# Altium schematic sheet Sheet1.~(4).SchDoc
size A4
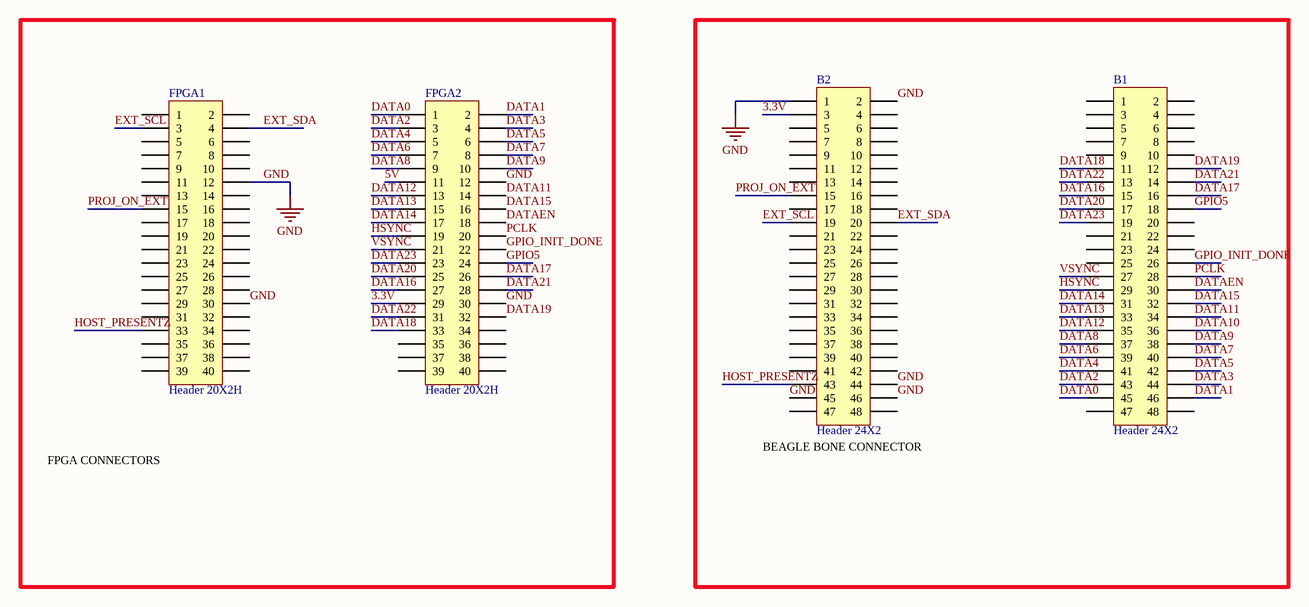
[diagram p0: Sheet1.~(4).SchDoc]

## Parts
B1  Header 24X2  [HDR2X24]
B2  Header 24X2  [HDR2X24]
FPGA1  Header 20X2H  [HDR2X20H]
FPGA2  Header 20X2H  [HDR2X20H]

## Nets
GND: B2.1 B2.2 B2.44 B2.45 B2.46 FPGA1.12 FPGA1.30 FPGA2.12 FPGA2.30
3.3V: B2.3 FPGA2.29
5V: FPGA2.11
DATA0: B1.45 FPGA2.1
DATA1: B1.46 FPGA2.2
DATA2: B1.43 FPGA2.3
DATA3: B1.44 FPGA2.4
DATA4: B1.41 FPGA2.5
DATA5: B1.42 FPGA2.6
DATA6: B1.39 FPGA2.7
DATA7: B1.40 FPGA2.8
DATA8: B1.37 FPGA2.9
DATA9: B1.38 FPGA2.10
DATA10: B1.36
DATA11: B1.34 FPGA2.14
DATA12: B1.35 FPGA2.13
DATA13: B1.33 FPGA2.15
DATA14: B1.31 FPGA2.17
DATA15: B1.32 FPGA2.16
DATA16: B1.15 FPGA2.27
DATA17: B1.16 FPGA2.26
DATA18: B1.11 FPGA2.33
DATA19: B1.12 FPGA2.32
DATA20: B1.17 FPGA2.25
DATA21: B1.14 FPGA2.28
DATA22: B1.13 FPGA2.31
DATA23: B1.19 FPGA2.23
DATAEN: B1.30 FPGA2.18
EXT_SCL: B2.19 FPGA1.3
EXT_SDA: B2.20 FPGA1.4
GPIO5: B1.18 FPGA2.24
GPIO_INIT_DONE: B1.26 FPGA2.22
HOST_PRESENTZ: B2.43 FPGA1.33
HSYNC: B1.29 FPGA2.19
PCLK: B1.28 FPGA2.20
PROJ_ON_EXT: B2.15 FPGA1.15
VSYNC: B1.27 FPGA2.21

Not connected (* = marked no-connect by the designer): B1 1 2 3 4 5 6 7 8 9 10 20 21 22 23 24 25 47 48; B2 4 5 6 7 8 9 10 11 12 13 14 16 17 18 21 22 23 24 25 26 27 28 29 30 31 32 33 34 35 36 37 38 39 40 41 42 47 48; FPGA1 1 2 5 6 7 8 9 10 11 13 14 16 17 18 19 20 21 22 23 24 25 26 27 28 29 31 32 34 35 36 37 38 39 40; FPGA2 34 35 36 37 38 39 40

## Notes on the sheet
- FPGA CONNECTORS
- BEAGLE BONE CONNECTOR

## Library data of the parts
B1 B2 = Header 24X2: Header, 24-Pin, Dual row
FPGA1 FPGA2 = Header 20X2H: Header, 20-Pin, Dual row, Right Angle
